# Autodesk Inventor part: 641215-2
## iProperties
Shininess: 64.0
Length Units: 11272
Angle Units: 11279
Time Units: 11290
Mass Units: 11286
Length Display Precision: 3
Angle Display Precision: 2
Compacted: True
Part Number: 641215-2
Document SubType Name: Modeling
Created: 2004-02
Designer: RRomano
Manufacturer: Standard
Standards Organization: Custom
Description: MTA100  2 PINS WITH RAMP
Vendor: AMP
Density: 0.0
Volumn: 0.0
Area: 0.0
PropertySet Name: Model Information
Control State: 0
Master: False
Checked Out: False
Author: RRomano
Title: MTA 100 STRAIGHT
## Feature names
1. Extrusion1
2. Extrusion6
3. Extrusion7
4. Extrusion8
5. Rectangular Pattern6
6. Rectangular Pattern4
7. Extrusion9
8. Chamfer2
9. Extrusion10
10. Chamfer3
11. Rectangular Pattern5
